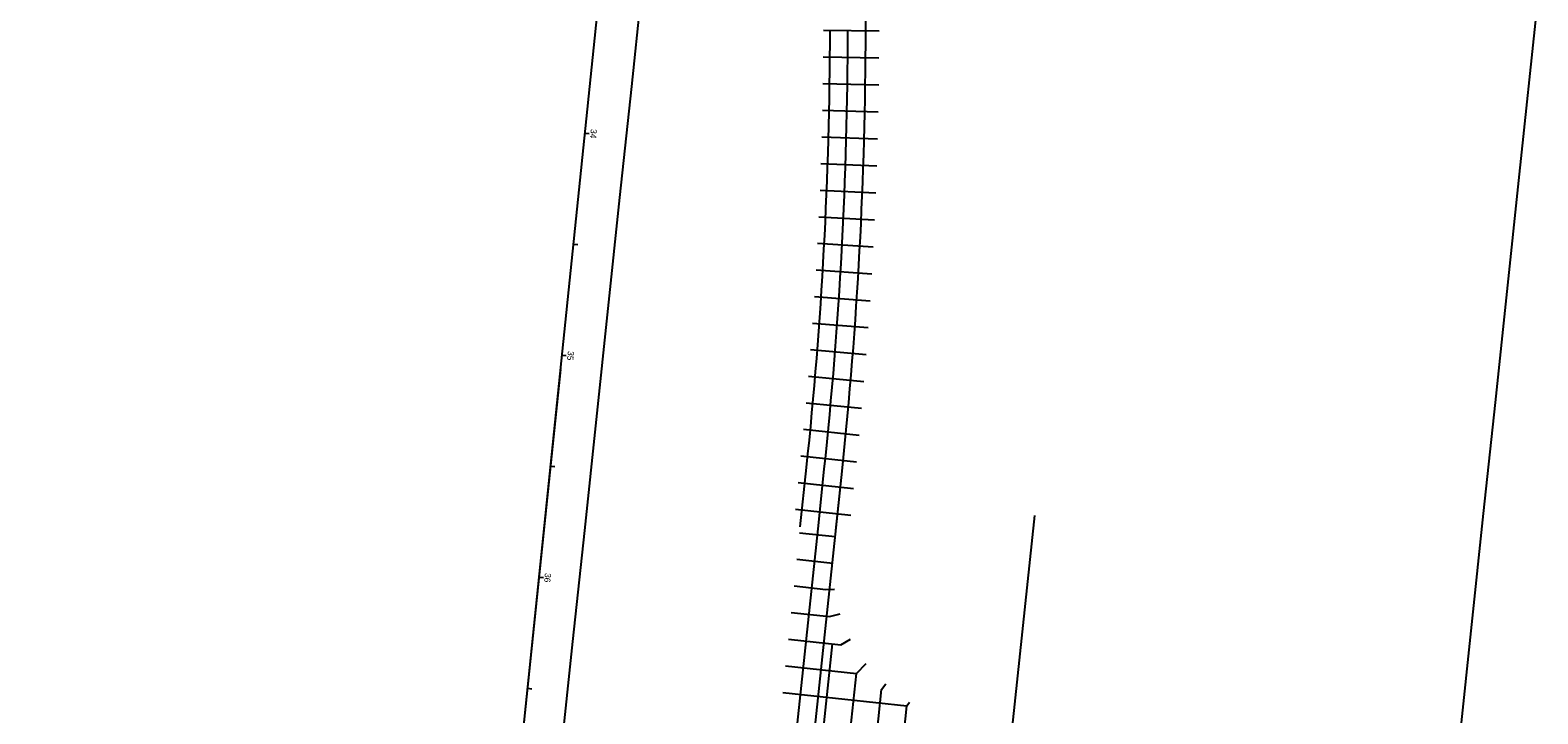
# Model space of a CAD drawing. Extents: x 172043 to 172847, y 249504 to 259737.
# Drawn here: x 172171 to 172847, y 256080 to 256386 of the extents above; entities that cross this region are included whole.
import ezdxf

# ---------------------------------------------------------------- set-up
doc = ezdxf.new("R2010")
doc.units = 0
for name, color, linetype in [('PM_X_Surveyed_Line', 7, 'Continuous'), ('PV_X_EOP', 7, 'Continuous'), ('PV_X_Shoulder', 7, 'Continuous'), ('RW_X_CL_100_Distances', 7, 'Continuous')]:
    doc.layers.add(name, color=color, linetype=linetype)

msp = doc.modelspace()

# ---------------------------------------------------------------- linework, layer by layer
at = {"layer": 'PM_X_Surveyed_Line'}
for p, q in [((172428.67, 256423.35), (172177.28, 253990.91)), ((172420.05, 256339.98), (172422.04, 256339.78)), ((172420.05, 256339.98), (172422.04, 256339.78)), ((172414.91, 256290.25), (172416.9, 256290.04)), ((172409.77, 256240.51), (172411.76, 256240.31)), ((172409.77, 256240.51), (172411.76, 256240.31)), ((172409.1, 256234.03), (172171.47, 253934.66)), ((172404.63, 256190.78), (172406.62, 256190.57)), ((172399.49, 256141.04), (172401.48, 256140.84)), ((172399.49, 256141.04), (172401.48, 256140.84)), ((172394.35, 256091.31), (172396.34, 256091.1))]:
    msp.add_line(p, q, dxfattribs=at)
at = {"layer": 'PV_X_EOP'}
for p, q in [((172545.97, 256386.02), (172546.38, 256601.68)), ((172520.75, 256050.68), (172535.35, 256188.54)), ((172553.71, 255526.79), (172621.69, 256168.73))]:
    msp.add_line(p, q, dxfattribs=at)
msp.add_arc((170636.1, 256389.67), 1909.87, 353.95499, 359.89076, dxfattribs=at)
at = {"layer": 'PV_X_Shoulder'}
msp.add_lwpolyline([(172393.52, 255913.31), (172791.29, 255871.19), (172796.56, 255920.91), (172801.83, 255970.63), (172807.09, 256020.35), (172812.36, 256070.07), (172817.62, 256119.8), (172822.89, 256169.52), (172828.15, 256219.24), (172833.42, 256268.96), (172838.68, 256318.68), (172847.18, 256398.96), (172445.03, 256399.72), (172440.91, 256360.81), (172435.64, 256311.09), (172430.38, 256261.36), (172425.11, 256211.64), (172419.85, 256161.92), (172414.58, 256112.2), (172409.32, 256062.48), (172404.05, 256012.75), (172398.78, 255963.03)], close=True, dxfattribs=at)
at = {"layer": 'RW_X_CL_100_Distances'}
for p, q in [((172545.97, 256386.02), (172546.38, 256601.68)), ((172551.96, 256385.53), (172526.97, 256385.83)), ((172551.9, 256373.44), (172526.9, 256373.9)), ((172551.76, 256361.35), (172526.77, 256361.97)), ((172551.54, 256349.26), (172526.55, 256350.04)), ((172551.25, 256337.18), (172526.27, 256338.12)), ((172550.88, 256325.1), (172525.9, 256326.19)), ((172550.44, 256313.02), (172525.47, 256314.27)), ((172549.91, 256300.94), (172524.95, 256302.35)), ((172549.32, 256288.87), (172524.36, 256290.43)), ((172548.64, 256276.8), (172523.7, 256278.52)), ((172547.89, 256264.73), (172522.96, 256266.61)), ((172547.06, 256252.67), (172522.15, 256254.71)), ((172546.16, 256240.62), (172521.26, 256242.81)), ((172545.18, 256228.57), (172520.29, 256230.92)), ((172544.13, 256216.53), (172519.25, 256219.04)), ((172543, 256204.51), (172518.14, 256207.14)), ((172541.8, 256192.57), (172516.94, 256195.2)), ((172516.62, 256163.59), (172519.44, 256190.22)), ((172524.57, 256162.75), (172527.39, 256189.38)), ((172524.57, 256162.75), (172527.39, 256189.38)), ((172532.53, 256161.91), (172535.35, 256188.54)), ((172540.54, 256180.62), (172515.69, 256183.28)), ((172539.28, 256168.69), (172514.42, 256171.35)), ((172452.27, 255479.94), (172524.57, 256162.75)), ((172516.34, 256160.98), (172532.25, 256159.3)), ((172515.08, 256149.05), (172531.22, 256147.34)), ((172513.81, 256137.11), (172528.1, 256135.6)), ((172528.1, 256135.6), (172531.93, 256135.65)), ((172512.55, 256125.18), (172529.74, 256123.36)), ((172529.74, 256123.36), (172534.47, 256124.58)), ((172464.14, 255478.68), (172531.12, 256111.15)), ((172511.29, 256113.25), (172534.82, 256110.75)), ((172534.82, 256110.75), (172539.19, 256113.22)), ((172476.07, 255477.42), (172541.79, 256097.95)), ((172510.02, 256101.31), (172541.79, 256097.95)), ((172541.79, 256097.95), (172546.22, 256102.39)), ((172488.01, 255476.16), (172553.09, 256090.72)), ((172553.09, 256090.72), (172554.9, 256093.21)), ((172499.94, 255474.89), (172564.39, 256083.49)), ((172508.76, 256089.38), (172564.39, 256083.49)), ((172564.39, 256083.49), (172565.55, 256085.08))]:
    msp.add_line(p, q, dxfattribs=at)
for radius in [1893.87, 1901.87, 1901.87, 1909.87]:
    msp.add_arc((170636.1, 256389.67), radius, 353.95499, 359.89076, dxfattribs=at)

# ---------------------------------------------------------------- texts
at = {"layer": 'PM_X_Surveyed_Line'}
for s, p in [('34', (172422.76, 256341.87)), ('35', (172412.48, 256242.43)), ('36', (172402.21, 256143.02))]:
    msp.add_text(s, height=2.8, rotation=264.09958, dxfattribs=at).set_placement(p)

doc.saveas('drawing.dxf')
